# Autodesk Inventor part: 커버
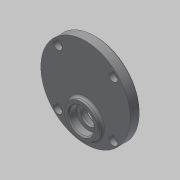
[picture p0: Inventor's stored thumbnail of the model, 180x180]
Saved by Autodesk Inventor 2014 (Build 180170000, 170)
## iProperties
Created: 2014-12
Part Number: 커버
Material: Generic
Document SubType Name: Modeling
Designer: user
Density: 1 g/cm^3
Appearance: Default
Author: user
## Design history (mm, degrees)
sketch "스케치2"
  geometry: C1 r 40 at (0, 0); 1 further point
  constraints: 1 centre point, 1 coincident
  dimensions: "d0" = 80 diameter of C1
extrude "돌출1" new body sketch "스케치2" distance "d1" = 9; taper "d2" = 0 deg
sketch "스케치3"
  geometry: C1 r 40 at (0, 0) reference; C2 r 15 at (0, -20)
  constraints: 1 centre point, 1 vertical alignment
  dimensions: "d3" = 30 diameter of C2; "d4" = 20 distance of C2.centre C1.centre
extrude "돌출2" join sketch "스케치3" distance "d5" = 4; taper "d6" = 0 deg
sketch "스케치4"
  geometry: C1 r 40 at (0, 0) reference; C2 r 14 at (0, -11); C3 r 14 at (0, 20)
  constraints: 2 centre point, 2 vertical alignment
  dimensions: "d7" = 28 diameter of C2; "d8" = 28 diameter of C3; "d9" = 11 distance of C1.centre C2.centre; "d10" = 20 distance of C3.centre C1.centre
extrude "돌출3" join sketch "스케치4" distance "d11" = 3; taper "d12" = 0 deg
sketch "스케치5"
  geometry: C1 r 14 at (0, 0) reference; C2 r 11 at (0, 0); 1 further point
  constraints: 1 centre point, 1 coincident
  dimensions: "d13" = 22 diameter of C2
extrude "돌출4" cut sketch "스케치5" distance "d14" = 7; taper "d15" = 0 deg
sketch "스케치6"
  geometry: C1 r 9 at (0, 0); 2 further points
  constraints: 1 centre point, 1 coincident, 1 vertical alignment
  dimensions: "d16" = 18 diameter of C1
extrude "돌출5" cut sketch "스케치6" distance "d17" = 1; taper "d18" = 0 deg
fillet "모깎기1" dims "d19" = 2
fillet "모깎기2" dims "d20" = 0.3
chamfer "모따기1" distance "d21" = 1; stored, may be unused: second distance "d22" = 2, angle "d23" = 45 deg
sketch "스케치7"
  geometry: C1 r 14 at (0, 0) reference; C2 r 11 at (0, 0); 1 further point
  constraints: 1 centre point, 1 coincident
  dimensions: "d24" = 22 diameter of C2
extrude "돌출6" cut sketch "스케치7" distance "d25" = 7; taper "d26" = 0 deg
sketch "스케치8"
  geometry: C1 r 11 at (0, 0) reference; C2 r 7.5 at (0, 0); 1 further point
  constraints: 1 centre point, 1 coincident
  dimensions: "d27" = 15 diameter of C2
extrude "돌출7" cut sketch "스케치8" distance "d28" = 2; taper "d29" = 0 deg
sketch "스케치9"
  geometry: C1 r 15 at (0, 0) reference; C2 r 11 at (0, 0); 1 further point
  constraints: 1 centre point, 1 coincident
  dimensions: "d30" = 22 diameter of C2
extrude "돌출8" cut sketch "스케치9" distance "d31" = 7; taper "d32" = 0 deg
chamfer "모따기2" distance "d33" = 1; stored, may be unused: second distance "d34" = 2, angle "d35" = 45 deg
fillet "모깎기3" dims "d36" = 0.3
fillet "모깎기4" dims "d37" = 2
chamfer "모따기3" distance "d38" = 1; stored, may be unused: second distance "d39" = 2, angle "d40" = 45 deg
sketch "스케치10"
  geometry: L1 (-24.749, 24.749)-(24.749, -24.749); L2 (24.749, 24.749)-(-24.749, -24.749); L3 (-35, 0)-(35, 0); C1 r 40 at (0, 0) reference; A1 r 35 centre (0, 0) between (-24.749, 24.749) and (24.749, -24.749); 6 further points
  constraints: 7 coincident, 6 end point, 6 point on circle, 3 midpoint, 1 centre point, 1 horizontal
  dimensions: "d41" = 70 diameter of A1; "d42" = 45 deg angle of L2 L3; "d43" = 90 deg angle of L1 L2
hole "구멍1" sketch "스케치10" at (-24.749, 24.749), (24.749, 24.749), (24.749, -24.749), (-24.749, -24.749) diameter "d44" = 4.5; stored, may be unused: countersink angle "d48" = 90 deg, drill point angle "d50" = 118 deg; dims "d45" = 6, "d46" = 8, "d47" = 4.4, "d49" = 8
node "솔리드1"
